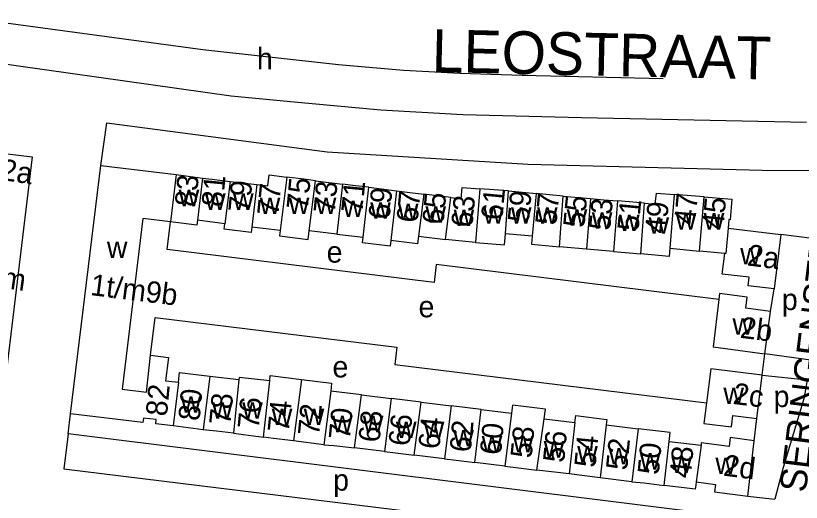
# Model space of a CAD drawing. Extents: x 161258 to 163262, y 380749 to 382054.
# Drawn here: x 161998.1 to 162145.4, y 381542.2 to 381633.4 of the extents above; entities that cross this region are included whole.
import ezdxf

# ---------------------------------------------------------------- set-up
doc = ezdxf.new("R2010")
doc.units = 0
for name, color, linetype in [('BLT_Basislijn', 7, 'Continuous'), ('BLT_Bebouwing', 7, 'Continuous'), ('BLT_Centroide', 7, 'Continuous'), ('BLT_Huisnummer', 7, 'Continuous'), ('BLT_Huisnummer_ tussenligend', 7, 'Continuous'), ('BLT_Huisnummer_reeks', 7, 'Continuous'), ('BLT_Onderverdeling_panden', 7, 'Continuous'), ('BLT_Straatnaam', 7, 'Continuous'), ('BLT_Straatnaam_hoofdweg', 7, 'Continuous')]:
    doc.layers.add(name, color=color, linetype=linetype)

msp = doc.modelspace()

# ---------------------------------------------------------------- linework, layer by layer
at = {"layer": 'BLT_Basislijn'}
for p, q in [((162104.2, 381614.33), (162146.38, 381613.45)), ((162147.43, 381591.67), (162141.57, 381592.38)), ((162139.64, 381577.98), (162140.32, 381582.21)), ((162138.07, 381566.04), (162138.55, 381570.04)), ((162147.21, 381568.86), (162138.55, 381570.04)), ((162138.07, 381566.04), (162146.53, 381565.15)), ((162007.95, 381555.02), (162008.43, 381558.82)), ((162136.58, 381553.75), (162137.1, 381557.93)), ((162139.36, 381538.7), (162007.95, 381555.02)), ((162135.39, 381543.39), (162140.44, 381542.78))]:
    msp.add_line(p, q, dxfattribs=at)
for points in [[(161986.51, 381633.39), (162033.24, 381627.05), (162058.66, 381624.22), (162070.84, 381623.16), (162081.43, 381622.63), (162093.08, 381622.28), (162119.5, 381621.62)], [(161983.51, 381626.15), (162038.53, 381618.39), (162049.65, 381617.33), (162066.6, 381615.74), (162081.96, 381614.86), (162104.2, 381614.33)], [(162014.07, 381605.31), (162015.22, 381613.31), (162056.55, 381607.87), (162094.19, 381605.56), (162138.1, 381604.46), (162156.3, 381604.36)], [(162129.96, 381580.23), (162076.98, 381586.76), (162076.56, 381583.41), (162026.5, 381589.56), (162027.14, 381594.76)], [(162023.43, 381569.81), (162024.29, 381576.84), (162069.6, 381571.28), (162069.21, 381568.06), (162127.63, 381560.87)], [(162146.53, 381565.15), (162145.86, 381561.63), (162142.02, 381548.74), (162140.44, 381542.78)], [(162007.95, 381555.02), (162007.16, 381548.48), (162138.41, 381532.36)]]:
    msp.add_lwpolyline(points, dxfattribs=at)
at = {"layer": 'BLT_Bebouwing'}
for p, q in [((162028.2, 381603.61), (162033.17, 381602.98)), ((162038.33, 381602.35), (162043.35, 381601.75)), ((162054.31, 381602.44), (162059.38, 381601.84)), ((162064.36, 381601.24), (162069.54, 381600.6)), ((162090.54, 381600.56), (162085.17, 381600.95)), ((162090.54, 381600.56), (162095.67, 381600.05)), ((162079.68, 381599.35), (162074.62, 381599.97)), ((162100.76, 381599.6), (162105.88, 381599.14)), ((162116.02, 381598.27), (162110.93, 381598.69)), ((162127.17, 381599.43), (162121.57, 381599.87)), ((162037.36, 381594.41), (162032.21, 381595.05)), ((162058.36, 381592.44), (162053.17, 381593.07)), ((162058.36, 381592.44), (162063.24, 381591.87)), ((162105.15, 381589.66), (162100.07, 381590.11)), ((162120.73, 381589.83), (162126.29, 381589.28)), ((162110.21, 381589.21), (162105.15, 381589.66)), ((162110.21, 381589.21), (162115.3, 381588.76)), ((162131.04, 381588.86), (162126.29, 381589.28)), ((162034.55, 381565.84), (162039.99, 381565.2)), ((162062.95, 381562.36), (162057.18, 381563.06)), ((162062.95, 381562.36), (162068.49, 381561.68)), ((162074.14, 381560.99), (162068.49, 381561.68)), ((162074.14, 381560.99), (162079.79, 381560.3)), ((162085.36, 381559.62), (162079.79, 381560.3)), ((162085.36, 381559.62), (162091.1, 381558.92)), ((162097.21, 381557.86), (162102.95, 381557.16)), ((162033.29, 381555.79), (162027.63, 381556.52)), ((162108.84, 381556.73), (162114.85, 381555.99)), ((162038.95, 381555.14), (162044.58, 381554.45)), ((162055.9, 381553), (162050.21, 381553.72)), ((162120.61, 381553.61), (162126.61, 381552.92)), ((162067.26, 381551.76), (162061.62, 381552.42)), ((162078.53, 381550.39), (162072.86, 381551.05)), ((162089.84, 381549.01), (162084.19, 381549.7)), ((162101.87, 381547.52), (162095.82, 381548.25)), ((162113.65, 381546.08), (162107.72, 381546.81))]:
    msp.add_line(p, q, dxfattribs=at)
for points in [[(161983.65, 381609.07), (162001.2, 381606.97), (161995.59, 381560.22)], [(162008.43, 381558.82), (162014.07, 381605.31)], [(162014.07, 381605.31), (162028.2, 381603.61)], [(162043.35, 381601.75), (162045.4, 381601.5), (162045.64, 381603.55), (162048.94, 381603.15)], [(162054.31, 381602.44), (162052.12, 381602.75), (162048.94, 381603.15)], [(162033.17, 381602.98), (162034.98, 381602.79), (162038.33, 381602.35)], [(162064.36, 381601.24), (162061.85, 381601.54), (162059.38, 381601.84)], [(162069.54, 381600.6), (162072.02, 381600.29), (162074.62, 381599.97)], [(162079.68, 381599.35), (162081.65, 381599.1), (162081.81, 381601.23), (162085.17, 381600.95)], [(162116.02, 381598.27), (162118.03, 381598.1), (162118.27, 381600.15), (162121.57, 381599.87)], [(162100.76, 381599.6), (162098.17, 381599.81), (162095.67, 381600.05)], [(162105.88, 381599.14), (162108.39, 381598.91), (162110.93, 381598.69)], [(162127.17, 381599.43), (162132.4, 381598.99), (162132.05, 381595.16), (162131.82, 381595.19), (162131.68, 381593.6)], [(162027.14, 381594.76), (162021.96, 381595.38), (162018.12, 381563.41), (162022.65, 381562.86), (162023.43, 381569.81)], [(162032.21, 381595.05), (162032.1, 381594.17), (162027.14, 381594.76)], [(162042.38, 381593.8), (162042.26, 381592.78), (162037.24, 381593.39), (162037.36, 381594.41)], [(162047.73, 381593.15), (162042.38, 381593.8)], [(162047.73, 381593.15), (162047.6, 381592.15), (162052.97, 381591.48), (162053.1, 381592.49), (162053.17, 381593.07)], [(162131.68, 381593.6), (162141.57, 381592.38)], [(162068.47, 381591.24), (162068.35, 381590.21), (162063.12, 381590.84), (162063.24, 381591.87)], [(162073.66, 381592.11), (162073.48, 381590.63), (162068.47, 381591.24)], [(162073.66, 381592.11), (162078.71, 381591.47)], [(162084.35, 381590.92), (162078.71, 381591.47)], [(162084.35, 381590.92), (162089.77, 381590.43), (162089.94, 381592.51)], [(162094.98, 381592.1), (162089.94, 381592.51)], [(162094.98, 381592.1), (162094.84, 381590.57), (162100.07, 381590.11)], [(162141.57, 381592.38), (162140.32, 381582.21)], [(162120.73, 381589.83), (162120.62, 381588.28), (162115.3, 381588.76)], [(162135.43, 381582.79), (162135.62, 381584.37), (162130.57, 381584.98), (162131.04, 381588.86)], [(162140.32, 381582.21), (162135.43, 381582.79)], [(162139.64, 381577.98), (162134.98, 381578.62), (162135.26, 381580.65), (162130.1, 381581.36), (162129.96, 381580.23)], [(162129.96, 381580.23), (162128.89, 381571.36), (162138.55, 381570.04)], [(162138.55, 381570.04), (162139.64, 381577.98)], [(162023.43, 381569.81), (162026.77, 381569.36), (162026.24, 381564.99), (162028.62, 381564.71)], [(162028.62, 381564.71), (162028.85, 381566.51), (162034.55, 381565.84)], [(162138.07, 381566.04), (162128.42, 381567.24), (162127.63, 381560.87)], [(162045.75, 381565), (162040.03, 381565.63), (162039.99, 381565.2)], [(162045.75, 381565), (162045.86, 381565.97), (162051.73, 381565.24)], [(162051.73, 381565.24), (162057.36, 381564.54), (162057.18, 381563.06)], [(162137.1, 381557.93), (162138.07, 381566.04)], [(162097.21, 381557.86), (162097.44, 381559.66), (162091.29, 381560.44), (162091.1, 381558.92)], [(162127.63, 381560.87), (162127.14, 381556.98), (162132.3, 381556.33), (162132.57, 381558.49), (162137.1, 381557.93)], [(162027.63, 381556.52), (162024.37, 381556.92), (162024.45, 381557.71), (162022.06, 381558.01), (162021.97, 381557.2), (162008.43, 381558.82)], [(162102.95, 381557.16), (162103.12, 381558.49), (162108.96, 381557.72), (162108.84, 381556.73)], [(162120.61, 381553.61), (162120.82, 381555.27), (162114.85, 381555.99)], [(162038.95, 381555.14), (162035.77, 381555.53), (162033.29, 381555.79)], [(162050.21, 381553.72), (162046.46, 381554.17), (162044.58, 381554.45)], [(162055.9, 381553), (162057.8, 381552.88), (162061.62, 381552.42)], [(162136.58, 381553.75), (162132.08, 381554.34), (162131.86, 381552.66), (162126.66, 381553.33), (162126.61, 381552.92)], [(162135.39, 381543.39), (162136.58, 381553.75)], [(162067.26, 381551.76), (162069.34, 381551.47), (162072.86, 381551.05)], [(162078.53, 381550.39), (162080.68, 381550.12), (162084.19, 381549.7)], [(162089.84, 381549.01), (162092.38, 381548.68), (162095.82, 381548.25)], [(162107.72, 381546.81), (162104.25, 381547.21), (162101.87, 381547.52)], [(162113.65, 381546.08), (162115.96, 381545.85), (162119.67, 381545.36)], [(162125.71, 381546.04), (162125.65, 381545.44), (162125.53, 381544.69), (162123.42, 381544.93), (162119.67, 381545.36)], [(162125.71, 381546.04), (162129.32, 381545.57), (162129.14, 381544.2), (162135.39, 381543.39)]]:
    msp.add_lwpolyline(points, dxfattribs=at)
at = {"layer": 'BLT_Onderverdeling_panden'}
for p, q in [((162028.2, 381603.61), (162027.14, 381594.76)), ((162048.94, 381603.15), (162047.73, 381593.15)), ((162033.17, 381602.98), (162032.21, 381595.05)), ((162038.33, 381602.35), (162037.36, 381594.41)), ((162043.35, 381601.75), (162042.38, 381593.8)), ((162053.17, 381593.07), (162054.31, 381602.44)), ((162059.38, 381601.84), (162058.36, 381592.44)), ((162063.24, 381591.87), (162064.36, 381601.24)), ((162069.54, 381600.6), (162068.47, 381591.24)), ((162085.17, 381600.95), (162084.35, 381590.92)), ((162089.94, 381592.51), (162090.54, 381600.56)), ((162074.62, 381599.97), (162073.66, 381592.11)), ((162078.71, 381591.47), (162079.68, 381599.35)), ((162095.67, 381600.05), (162094.98, 381592.1)), ((162100.07, 381590.11), (162100.76, 381599.6)), ((162105.88, 381599.14), (162105.15, 381589.66)), ((162110.93, 381598.69), (162110.21, 381589.21)), ((162121.57, 381599.87), (162120.73, 381589.83)), ((162126.29, 381589.28), (162127.17, 381599.43)), ((162115.3, 381588.76), (162116.02, 381598.27)), ((162034.55, 381565.84), (162033.29, 381555.79)), ((162039.99, 381565.2), (162038.95, 381555.14)), ((162044.58, 381554.45), (162045.75, 381565)), ((162051.73, 381565.24), (162050.21, 381553.72)), ((162028.62, 381564.71), (162027.63, 381556.52)), ((162057.18, 381563.06), (162055.9, 381553)), ((162061.62, 381552.42), (162062.95, 381562.36)), ((162068.49, 381561.68), (162067.26, 381551.76)), ((162072.86, 381551.05), (162074.14, 381560.99)), ((162079.79, 381560.3), (162078.53, 381550.39)), ((162084.19, 381549.7), (162085.36, 381559.62)), ((162091.1, 381558.92), (162089.84, 381549.01)), ((162095.82, 381548.25), (162097.21, 381557.86)), ((162102.95, 381557.16), (162101.87, 381547.52)), ((162108.84, 381556.73), (162107.72, 381546.81)), ((162114.85, 381555.99), (162113.65, 381546.08)), ((162119.67, 381545.36), (162120.61, 381553.61)), ((162126.61, 381552.92), (162125.71, 381546.04))]:
    msp.add_line(p, q, dxfattribs=at)
msp.add_lwpolyline([(162131.68, 381593.6), (162131.26, 381588.84), (162131.04, 381588.86)], dxfattribs=at)

# ---------------------------------------------------------------- texts
at = {"layer": 'BLT_Centroide'}
for s, p in [('h', (162043.35, 381623.37)), ('w', (162028.68, 381597.7)), ('w', (162033.62, 381597.01)), ('w', (162038.87, 381597.01)), ('w', (162043.88, 381596.25)), ('w', (162049.32, 381596.25)), ('w', (162054.39, 381596.25)), ('w', (162059.46, 381595.68)), ('w', (162064.59, 381595.36)), ('w', (162069.78, 381595.13)), ('w', (162074.95, 381594.61)), ('w', (162085.77, 381594.43)), ('w', (162090.97, 381594.43)), ('w', (162095.86, 381594.43)), ('w', (162080.23, 381594)), ('w', (162101.42, 381594.03)), ('w', (162106.13, 381593.49)), ('w', (162111.23, 381593.02)), ('w', (162121.86, 381593.33)), ('w', (162127.11, 381593.33)), ('w', (162116.77, 381592.55)), ('w', (162015.22, 381588.01)), ('e', (162056.42, 381587.12)), ('w', (162133.95, 381586.8)), ('p', (162141.76, 381578.23)), ('e', (162073.65, 381576.88)), ('w', (162132.51, 381573.6)), ('e', (162057.52, 381565.61)), ('w', (162130.8, 381560.63)), ('w', (162029.06, 381559.01)), ('p', (162140.21, 381560.06)), ('w', (162034.94, 381557.9)), ('w', (162040.59, 381557.9)), ('w', (162046.13, 381556.68)), ('w', (162052.12, 381556.68)), ('w', (162057.44, 381555.35)), ('w', (162063.2, 381555.35)), ('w', (162069.41, 381554.24)), ('w', (162074.62, 381554.24)), ('w', (162080.16, 381552.69)), ('w', (162085.48, 381551.58)), ('w', (162091.35, 381551.58)), ('w', (162097.12, 381550.6)), ('w', (162103.39, 381549.7)), ('w', (162109.28, 381549.33)), ('w', (162115.14, 381548.36)), ('w', (162121.04, 381547.71)), ('w', (162129.3, 381547.52)), ('p', (162057.64, 381544.4))]:
    msp.add_text(s, height=4, dxfattribs=at).set_placement(p)
at = {"layer": 'BLT_Huisnummer'}
for s, rotation, p in [('83', 84.6085, (162031.92, 381597.49)), ('81', 84.6085, (162036.93, 381597.45)), ('77', 84.6085, (162047.36, 381595.83)), ('73', 84.6085, (162057.93, 381596.3)), ('69', 84.6085, (162068.21, 381595.1)), ('61', 84.6085, (162089.33, 381594.99)), ('65', 84.6085, (162078.3, 381594.16)), ('57', 84.6085, (162099.48, 381594.06)), ('53', 84.6085, (162109.55, 381593.05)), ('45', 84.6085, (162130.78, 381593.27)), ('49', 84.6085, (162120.04, 381592.45)), ('2a', 352.9937, (162135.12, 381586.61)), ('2b', 352.9937, (162133.8, 381573.05)), ('80', 84.6085, (162032.58, 381557.37)), ('2c', 352.9937, (162132.46, 381560.66)), ('76', 84.6085, (162043.69, 381555.83)), ('72', 84.6085, (162054.99, 381554.58)), ('68', 84.6085, (162066.34, 381553.33)), ('64', 84.6085, (162077.56, 381552.09)), ('60', 84.6085, (162089.1, 381550.98)), ('56', 84.6085, (162100.94, 381549.54)), ('52', 84.6085, (162112.75, 381548.12)), ('48', 84.6085, (162124.66, 381546.63)), ('2d', 352.9937, (162130.65, 381547.22))]:
    msp.add_text(s, height=4, rotation=rotation, dxfattribs=at).set_placement(p)
at = {"layer": 'BLT_Huisnummer_ tussenligend'}
for s, p in [('79', (162041.95, 381596.41)), ('75', (162052.87, 381596.96)), ('71', (162063.12, 381596.36)), ('67', (162073.47, 381594.5)), ('59', (162094.31, 381594.51)), ('63', (162083.72, 381593.61)), ('55', (162104.72, 381593.58)), ('51', (162114.87, 381592.93)), ('47', (162125.49, 381594.04)), ('78', (162038.36, 381556.58)), ('74', (162049.32, 381555.19)), ('70', (162060.77, 381553.81)), ('66', (162071.97, 381552.66)), ('62', (162083.43, 381551.48)), ('58', (162094.84, 381550.38)), ('54', (162106.81, 381548.63)), ('50', (162118.67, 381547.28))]:
    msp.add_text(s, height=4, rotation=84.6085, dxfattribs=at).set_placement(p)
at = {"layer": 'BLT_Huisnummer_reeks'}
for s, rotation, p in [('2a', 352, (161995.14, 381602.64)), ('t/m', 352, (161992.4, 381582.84)), ('1t/m9b', 352.9937, (162011.99, 381581.06)), ('82', 84.6085, (162026.47, 381558.23))]:
    msp.add_text(s, height=4, rotation=rotation, dxfattribs=at).set_placement(p)
at = {"layer": 'BLT_Straatnaam'}
msp.add_text('SERINGENSTRAAT', height=5, rotation=83.0026, dxfattribs=at).set_placement((162146.26, 381543.92))
at = {"layer": 'BLT_Straatnaam_hoofdweg'}
msp.add_text('LEOSTRAAT', height=8, rotation=358.7048, dxfattribs=at).set_placement((162076.07, 381622.86))

doc.saveas('drawing.dxf')
